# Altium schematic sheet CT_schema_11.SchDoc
size 741 x 377 mm
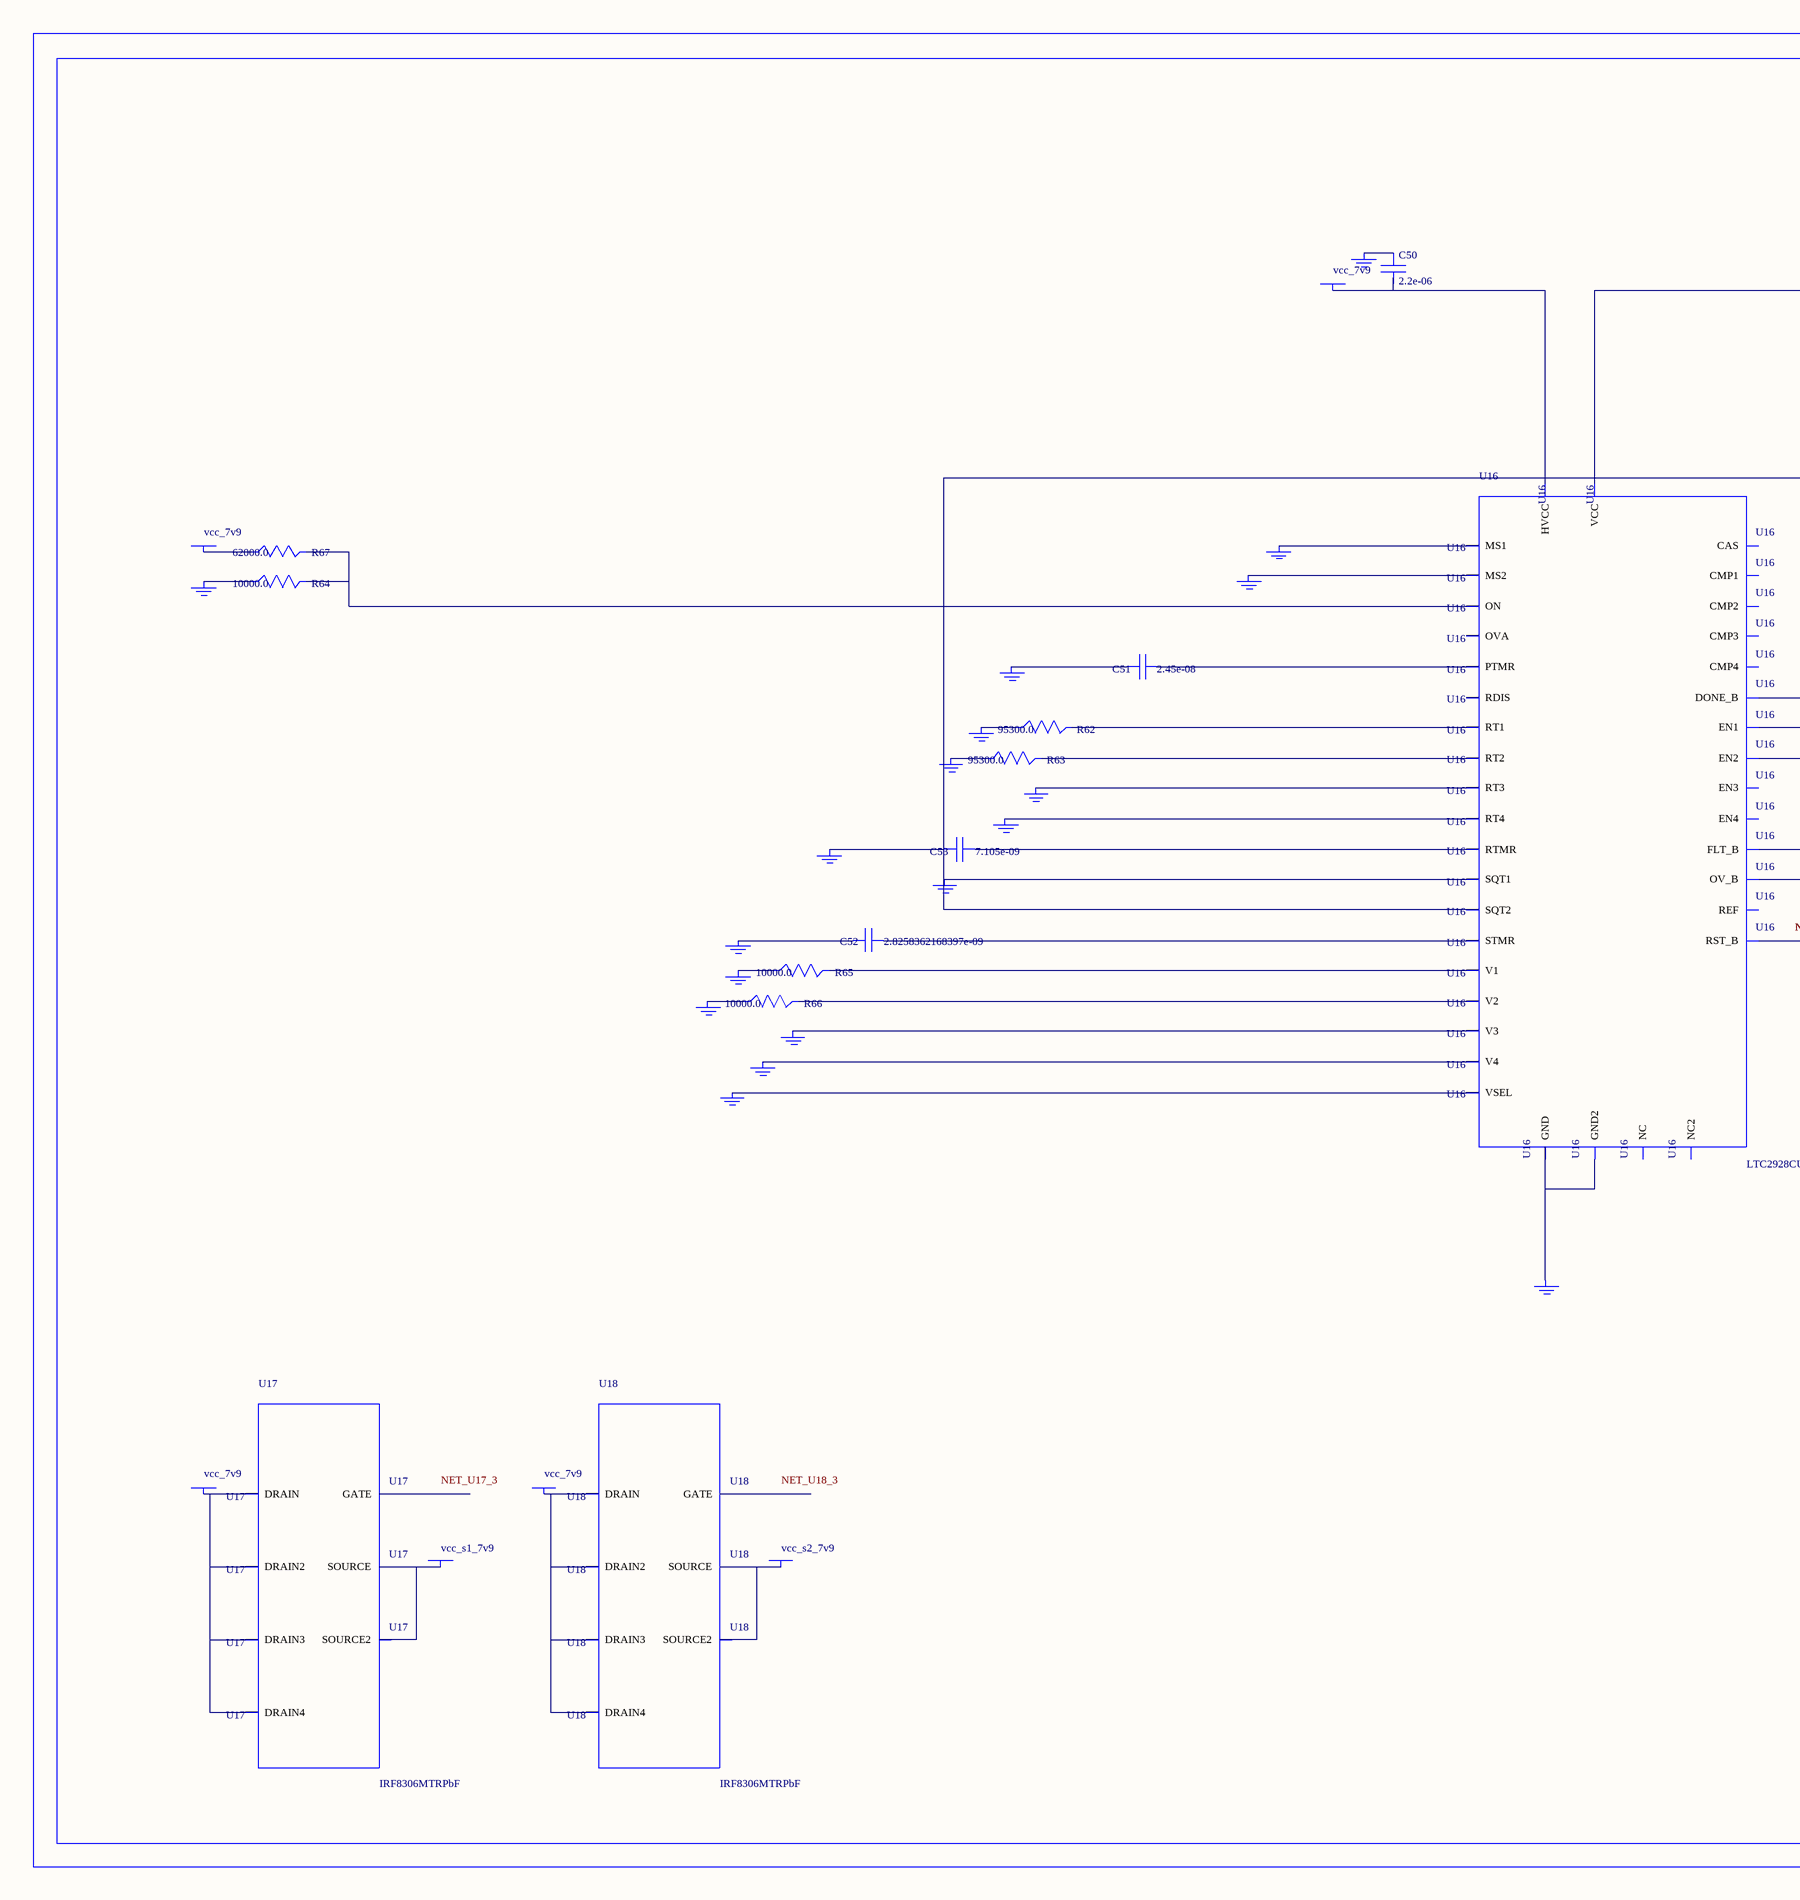
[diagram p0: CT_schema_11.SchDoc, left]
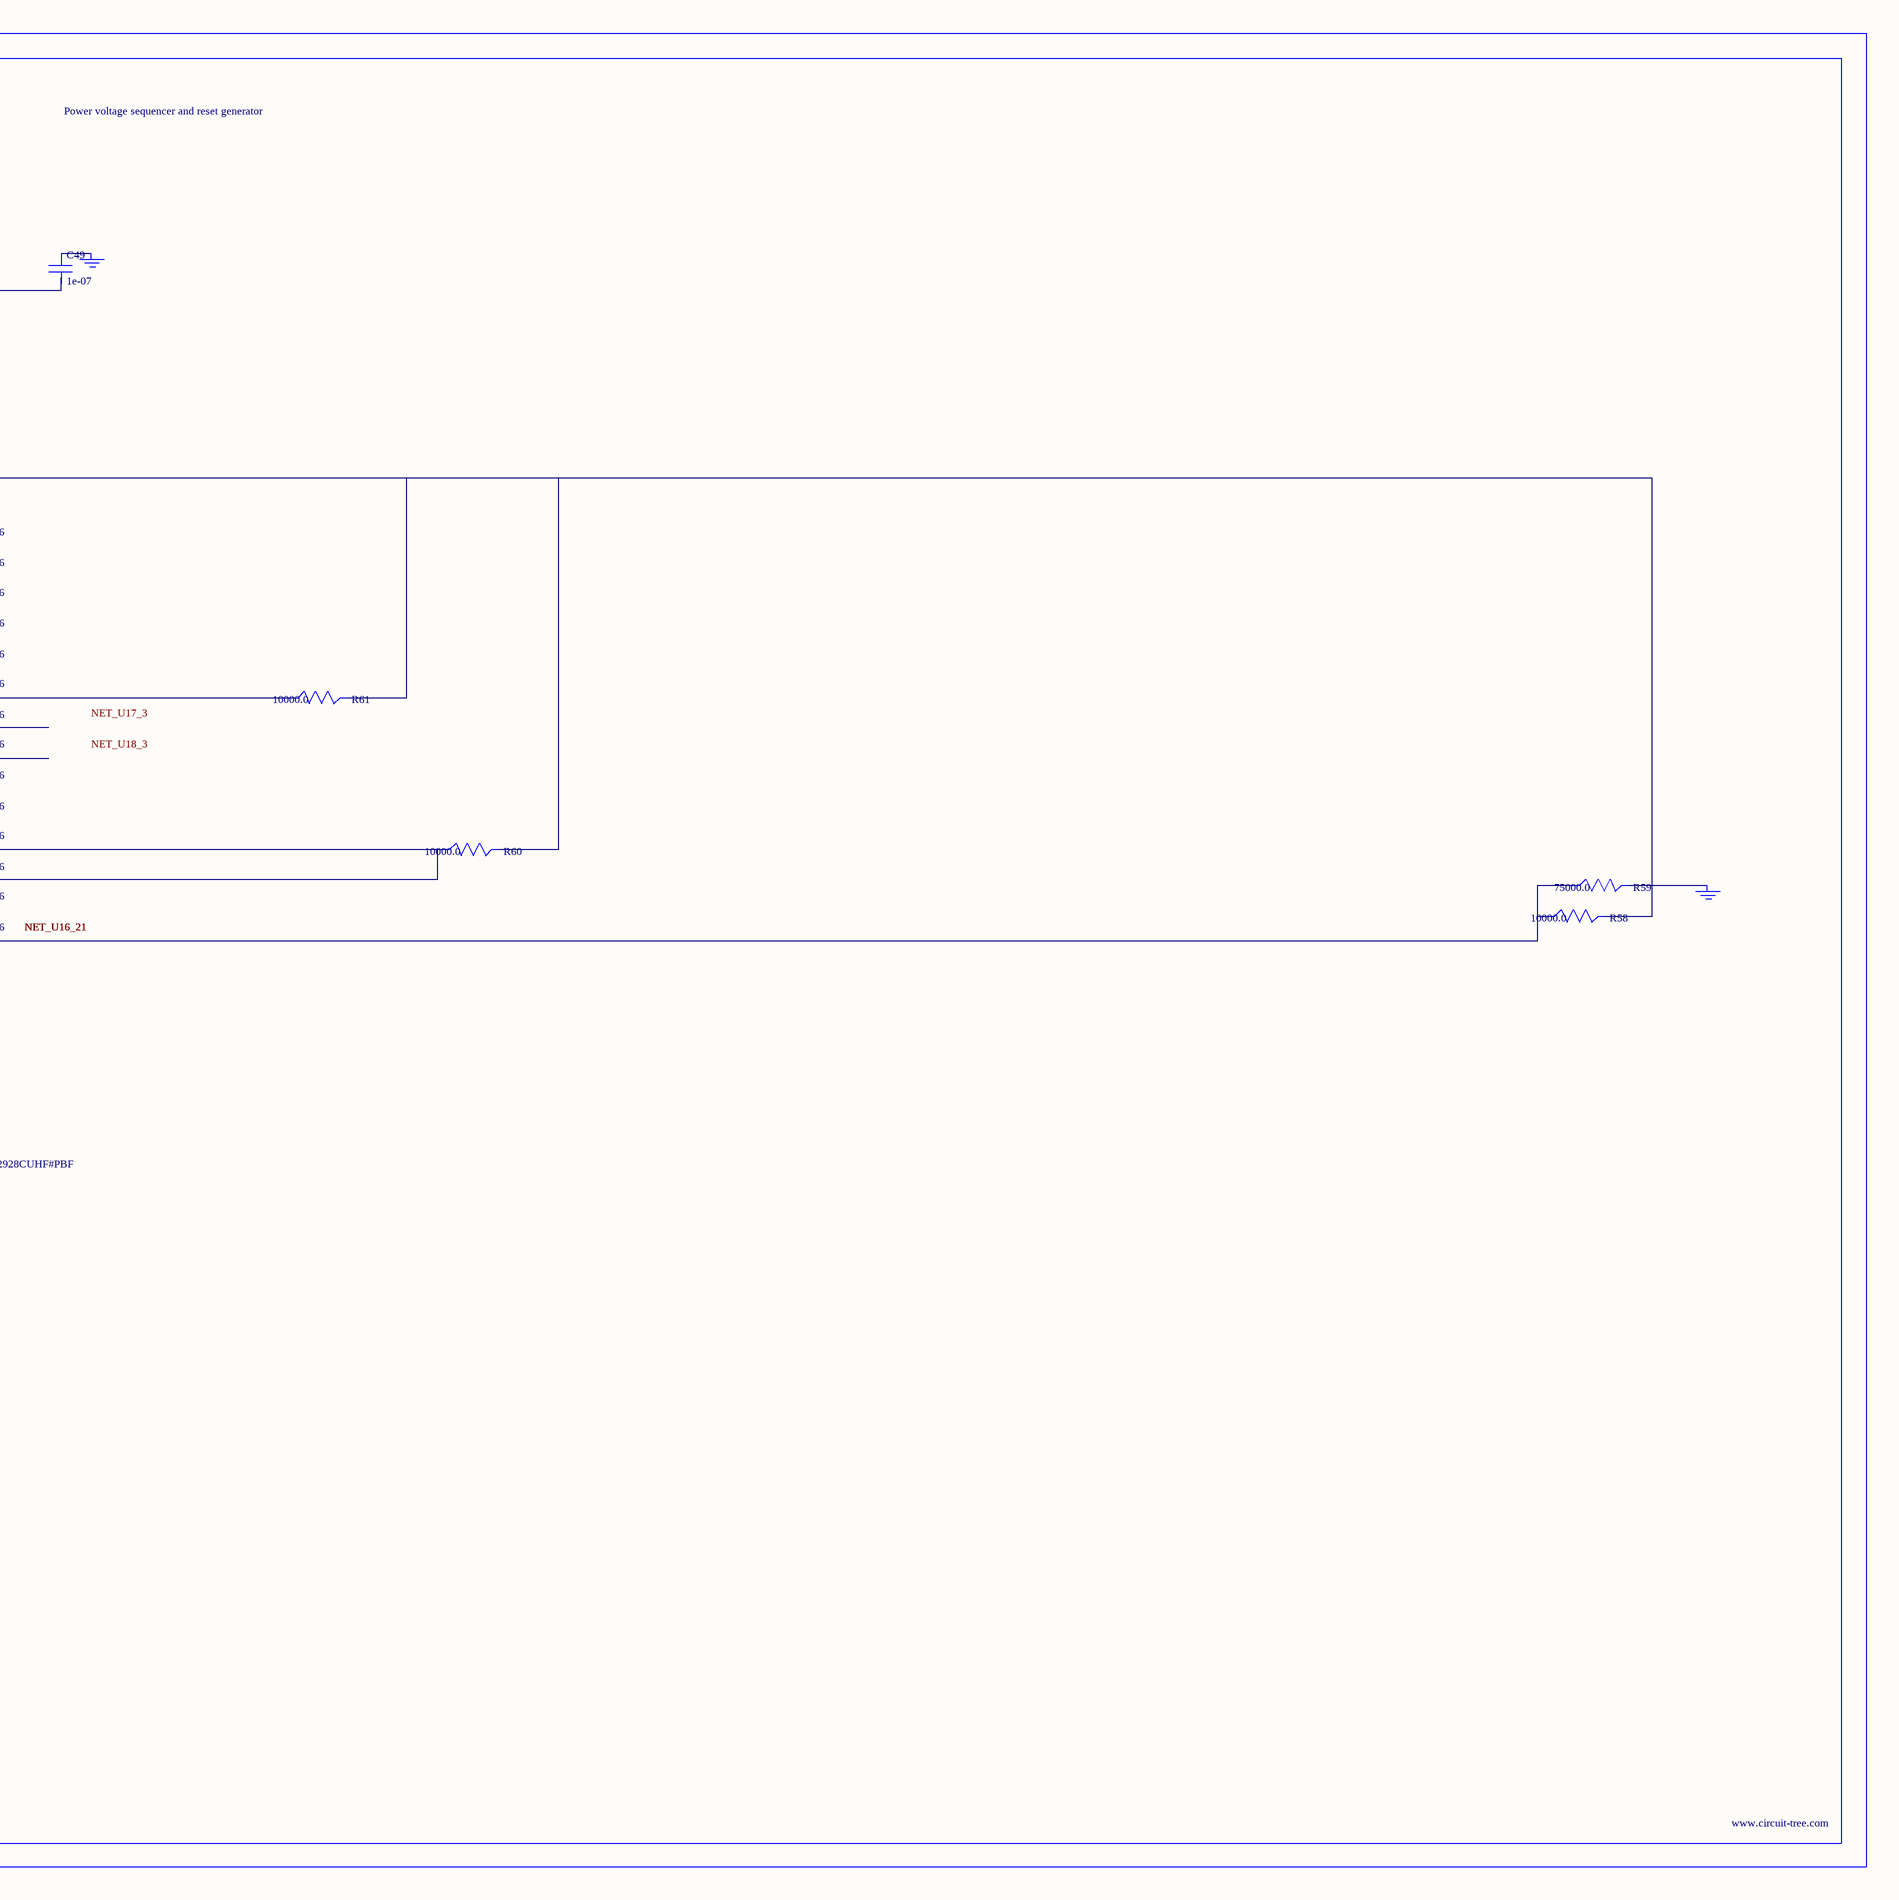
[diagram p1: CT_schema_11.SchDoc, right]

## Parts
BORDER10  (no value)
C49  1e-07  [C0402]
C50  2.2e-06  [C0603]
C51  2.45e-08  [R0603]
C52  2.8258362168397e-09  [R0603]
C53  7.105e-09  [R0603]
GND_INSTANCE_10_0  (no value)
GND_INSTANCE_10_1  (no value)
GND_INSTANCE_10_2  (no value)
GND_INSTANCE_10_3  (no value)
GND_INSTANCE_10_4  (no value)
GND_INSTANCE_10_5  (no value)
GND_INSTANCE_10_6  (no value)
GND_INSTANCE_10_7  (no value)
GND_INSTANCE_10_8  (no value)
GND_INSTANCE_10_9  (no value)
GND_INSTANCE_10_10  (no value)
GND_INSTANCE_10_11  (no value)
GND_INSTANCE_10_12  (no value)
GND_INSTANCE_10_13  (no value)
GND_INSTANCE_10_14  (no value)
GND_INSTANCE_10_15  (no value)
GND_INSTANCE_10_16  (no value)
GND_INSTANCE_10_17  (no value)
GND_INSTANCE_10_18  (no value)
GND_INSTANCE_10_19  (no value)
POWER_INSTANCE_10_0  vcc_7v9
POWER_INSTANCE_10_1  vcc_7v9
POWER_INSTANCE_10_2  vcc_7v9
POWER_INSTANCE_10_3  vcc_s1_7v9
POWER_INSTANCE_10_4  vcc_7v9
POWER_INSTANCE_10_5  vcc_s2_7v9
R58  10000.0  [R0603]
R59  75000.0  [R0603]
R60  10000.0  [R0603]
R61  10000.0  [R0603]
R62  95300.0  [R0603]
R63  95300.0  [R0603]
R64  10000.0  [R0603]
R65  10000.0  [R0603]
R66  10000.0  [R0603]
R67  62000.0  [R0603]
U16  LTC2928CUHF#PBF  [QFN-38_UHF]
U17  IRF8306MTRPbF  [IRF8306MTRPBF]
U18  IRF8306MTRPbF  [IRF8306MTRPBF]

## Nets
NetC49_1: C49.1 GND_INSTANCE_10_10.0(GND)
NetC49_2: C49.2 C53.2 GND_INSTANCE_10_5.0(GND) GND_INSTANCE_10_15.0(GND) R58.2 R60.2 R61.2 U16.10(SQT1) U16.11(SQT2) U16.22(VCC)
NetC50_1: C50.1 GND_INSTANCE_10_11.0(GND)
NetC50_2: C50.2 POWER_INSTANCE_10_1.0(PWR) U16.23(HVCC)
NetC51_1: C51.1 U16.27(PTMR)
NetC51_2: C51.2 GND_INSTANCE_10_14.0(GND)
NetC52_1: C52.1 U16.26(STMR)
NetC52_2: C52.2 GND_INSTANCE_10_13.0(GND)
NetC53_1: C53.1 U16.28(RTMR)
NetGND_INSTANCE_10_0_0: GND_INSTANCE_10_0.0(GND) R65.1
NetGND_INSTANCE_10_1_0: GND_INSTANCE_10_1.0(GND) R62.1
NetGND_INSTANCE_10_2_0: GND_INSTANCE_10_2.0(GND) R63.1
NetGND_INSTANCE_10_3_0: GND_INSTANCE_10_3.0(GND) U16.8(RT3)
NetGND_INSTANCE_10_4_0: GND_INSTANCE_10_4.0(GND) U16.9(RT4)
NetGND_INSTANCE_10_6_0: GND_INSTANCE_10_6.0(GND) U16.12(MS1)
NetGND_INSTANCE_10_7_0: GND_INSTANCE_10_7.0(GND) U16.13(MS2)
NetGND_INSTANCE_10_8_0: GND_INSTANCE_10_8.0(GND) R64.1
NetGND_INSTANCE_10_9_0: GND_INSTANCE_10_9.0(GND) R59.2
NetGND_INSTANCE_10_12_0: GND_INSTANCE_10_12.0(GND) U16.25(VSEL)
NetGND_INSTANCE_10_16_0: GND_INSTANCE_10_16.0(GND) U16.30(V4)
NetGND_INSTANCE_10_17_0: GND_INSTANCE_10_17.0(GND) U16.32(V3)
NetGND_INSTANCE_10_18_0: GND_INSTANCE_10_18.0(GND) R66.1
NetGND_INSTANCE_10_19_0: GND_INSTANCE_10_19.0(GND) U16.24(GND) U16.39(GND2)
NetPOWER_INSTANCE_10_0_0: POWER_INSTANCE_10_0.0(PWR) R67.1
NetPOWER_INSTANCE_10_2_0: POWER_INSTANCE_10_2.0(PWR) U17.1(DRAIN) U17.2(DRAIN2) U17.6(DRAIN3) U17.7(DRAIN4)
NetPOWER_INSTANCE_10_3_0: POWER_INSTANCE_10_3.0(PWR) U17.4(SOURCE) U17.5(SOURCE2)
NetPOWER_INSTANCE_10_4_0: POWER_INSTANCE_10_4.0(PWR) U18.1(DRAIN) U18.2(DRAIN2) U18.6(DRAIN3) U18.7(DRAIN4)
NetPOWER_INSTANCE_10_5_0: POWER_INSTANCE_10_5.0(PWR) U18.4(SOURCE) U18.5(SOURCE2)
NetR58_1: R58.1 R59.1 U16.21(RST_B)
NetR60_1: R60.1 U16.19(FLT_B) U16.20(OV_B)
NetR61_1: R61.1 U16.18(DONE_B)
NetR62_2: R62.2 U16.6(RT1)
NetR63_2: R63.2 U16.7(RT2)
NetR64_2: R64.2 R67.2 U16.16(ON)
NetR65_2: R65.2 U16.3(V1)
NetR66_2: R66.2 U16.38(V2)

Not connected (* = marked no-connect by the designer): U16 1(OVA) 2(EN1) 4(NC) 5(REF) 14(RDIS) 15(CAS) 17(NC2) 29(EN4) 31(EN3) 33(CMP3) 34(CMP4) 35(CMP1) 36(CMP2) 37(EN2); U17 3(GATE); U18 3(GATE)

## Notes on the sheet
- Labels drawn without touching a wire or pin: NET_U17_3, NET_U18_3

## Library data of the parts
BORDER10 = BORDER_PAGE10
C49 = C0402C104K3RACTU
C50 = GRM188R61H225KE1115D
C51 = C51
C52 = C52
C53 = C53
GND_INSTANCE_10_0-GND_INSTANCE_10_19 = GND
POWER_INSTANCE_10_0-POWER_INSTANCE_10_5 = PWR
R58 R60 R61 R64-R66 = RC0603JR-0710KL
R59 = RC0603JR-0775KL
R62 R63 = RC0603FR-0795K3L
R67 = RC0603JR-0762KL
